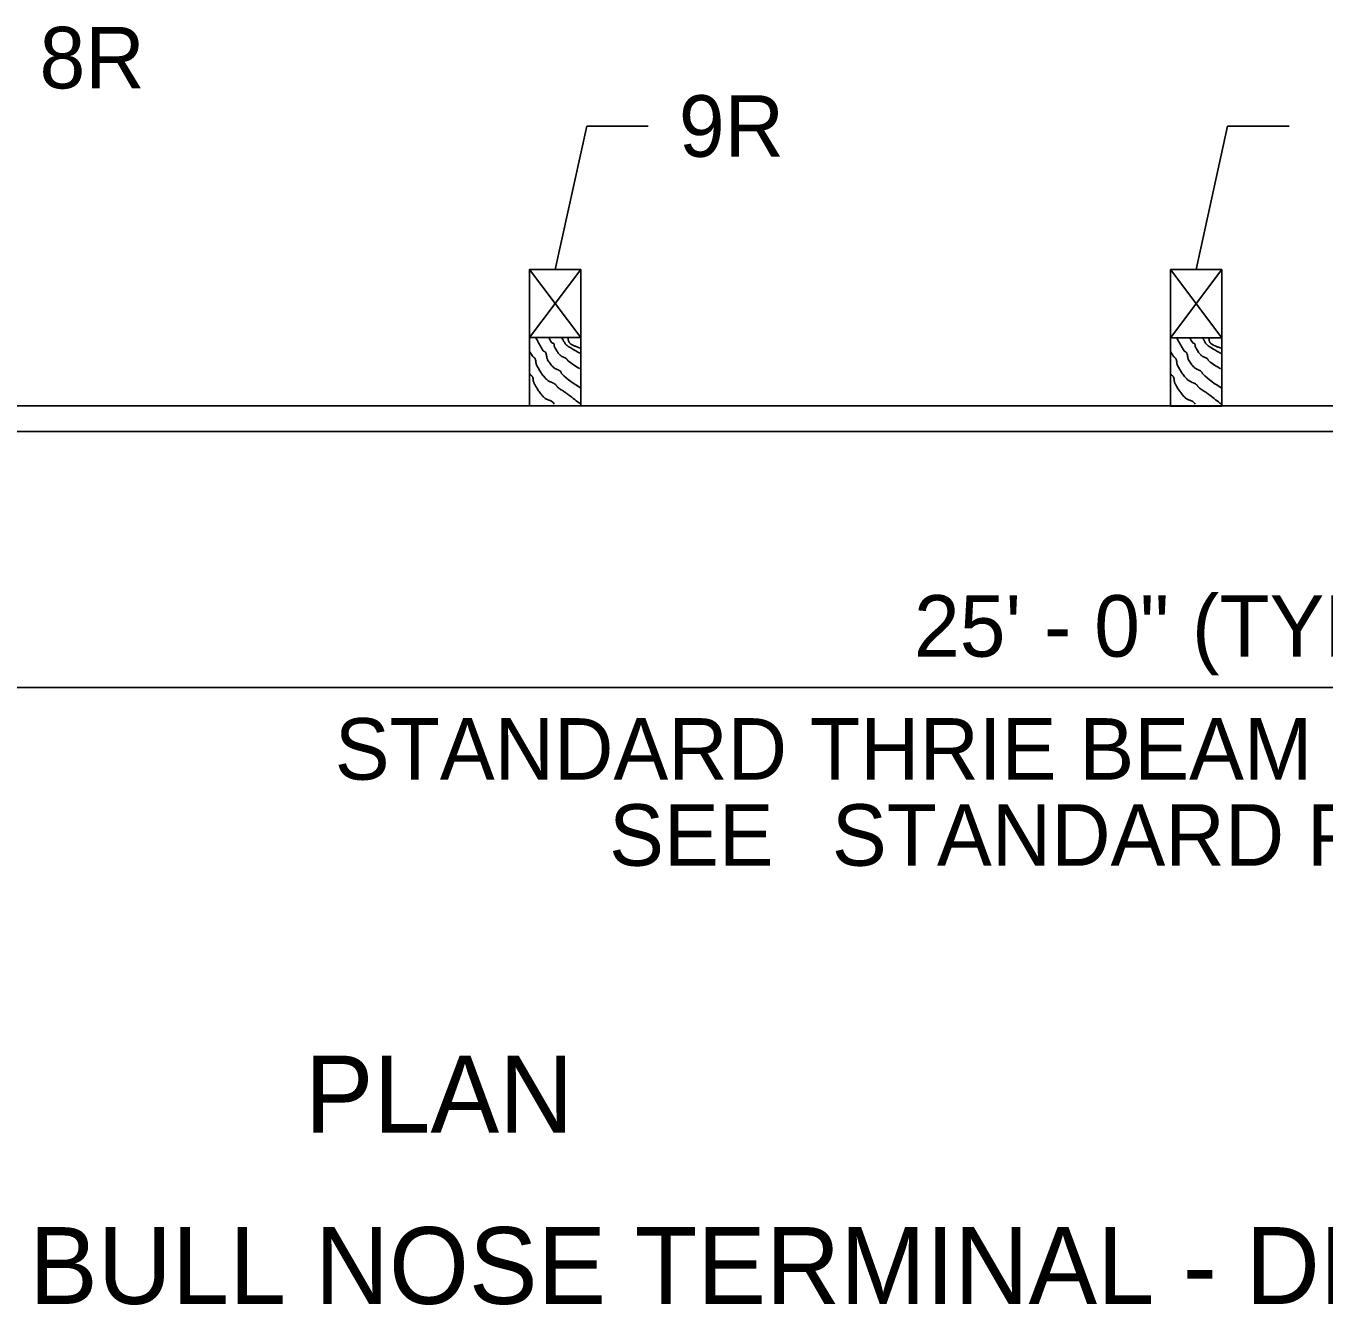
# Model space of a CAD drawing. Extents: x 1312564.2 to 1312581.5, y 1207298.4 to 1207352.6.
# Drawn here: x 1312570.058 to 1312571.742, y 1207304.86 to 1207306.519 of the extents above; entities that cross this region are included whole.
import ezdxf

# ---------------------------------------------------------------- set-up
doc = ezdxf.new("R2010")
doc.units = 0
for name, color, linetype in [('Level 13', 7, 'Continuous'), ('Level 14', 7, 'Continuous'), ('Level 15', 7, 'Continuous'), ('Level 20', 7, 'Continuous')]:
    doc.layers.add(name, color=color, linetype=linetype)

msp = doc.modelspace()

# ---------------------------------------------------------------- linework, layer by layer
at = {"layer": 'Level 13'}
for points in [[(1312570.7194039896, 1207306.1146937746), (1312570.7221586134, 1207306.1095615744), (1312570.7238268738, 1207306.106539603), (1312570.7255555, 1207306.1035501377), (1312570.727325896, 1207306.1005866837), (1312570.7291194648, 1207306.097642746), (1312570.7294023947, 1207306.0972981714), (1312570.7297603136, 1207306.0970238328), (1312570.7306033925, 1207306.096594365), (1312570.7314532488, 1207306.0961713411), (1312570.7321144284, 1207306.0955717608), (1312570.7324222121, 1207306.0950549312), (1312570.7326765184, 1207306.09451266), (1312570.7330540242, 1207306.093365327), (1312570.7334898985, 1207306.090914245), (1312570.7338912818, 1207306.0884350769), (1312570.734451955, 1207306.086687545), (1312570.7347274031, 1207306.0861443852), (1312570.7363016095, 1207306.0835514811), (1312570.738031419, 1207306.0810558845), (1312570.7399295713, 1207306.0786780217), (1312570.742008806, 1207306.076438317), (1312570.7430991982, 1207306.0755208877), (1312570.744308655, 1207306.0747590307), (1312570.746918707, 1207306.0734976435), (1312570.749506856, 1207306.0722453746), (1312570.750688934, 1207306.0714949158), (1312570.7517409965, 1207306.0705934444), (1312570.7521230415, 1207306.0699782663), (1312570.7523678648, 1207306.0692493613), (1312570.7526337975, 1207306.0685391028), (1312570.7530791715, 1207306.0679798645), (1312570.7779045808, 1207306.0494157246)], [(1312570.7362736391, 1207306.1146937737), (1312570.7401967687, 1207306.1081436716), (1312570.7404154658, 1207306.1079093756), (1312570.7407099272, 1207306.1077633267), (1312570.7414269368, 1207306.107619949), (1312570.7421493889, 1207306.1074814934), (1312570.7426788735, 1207306.1071159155), (1312570.7428199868, 1207306.1068721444), (1312570.7429332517, 1207306.106616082), (1312570.7430913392, 1207306.106073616), (1312570.7432394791, 1207306.104913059), (1312570.7433649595, 1207306.103738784), (1312570.7434947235, 1207306.1031791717), (1312570.743709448, 1207306.1026553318), (1312570.7445061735, 1207306.1011826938), (1312570.745331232, 1207306.0997201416), (1312570.7471061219, 1207306.0968591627), (1312570.7502295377, 1207306.0928550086), (1312570.7508198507, 1207306.0922347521), (1312570.7514334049, 1207306.0916307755), (1312570.7522992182, 1207306.0909426), (1312570.7532541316, 1207306.0903925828), (1312570.7553080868, 1207306.0895304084), (1312570.7573489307, 1207306.0886910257), (1312570.7587227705, 1207306.0878639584), (1312570.7589302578, 1207306.0876975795), (1312570.7591303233, 1207306.0875212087), (1312570.7596616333, 1207306.0868636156), (1312570.7601032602, 1207306.086107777), (1312570.7605681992, 1207306.0853746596), (1312570.761169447, 1207306.0847852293), (1312570.7763067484, 1207306.0745676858)], [(1312570.7531030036, 1207306.1146937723), (1312570.754498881, 1207306.1123594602), (1312570.7548076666, 1207306.1118255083), (1312570.755107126, 1207306.1112781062), (1312570.7568875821, 1207306.1079232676), (1312570.758294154, 1207306.1058972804), (1312570.7601158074, 1207306.1043224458), (1312570.7662563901, 1207306.1006090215), (1312570.776477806, 1207306.0944277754)], [(1312570.7610762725, 1207306.1146937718), (1312570.7613425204, 1207306.1129179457), (1312570.7616531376, 1207306.1111777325), (1312570.7621349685, 1207306.109574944), (1312570.7624797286, 1207306.1088569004), (1312570.7626850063, 1207306.1085242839), (1312570.7627967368, 1207306.108365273), (1312570.7628549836, 1207306.1082876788), (1312570.7628847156, 1207306.1082493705), (1312570.7628997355, 1207306.1082303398), (1312570.7629148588, 1207306.108211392), (1312570.7631970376, 1207306.107878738), (1312570.7634970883, 1207306.107560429), (1312570.76414729, 1207306.106964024), (1312570.7656234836, 1207306.1059123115), (1312570.7690821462, 1207306.1042152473), (1312570.772840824, 1207306.10275899), (1312570.774692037, 1207306.1020082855), (1312570.7764494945, 1207306.101182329)], [(1312571.5504640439, 1207306.1144906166), (1312571.5532186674, 1207306.1093584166), (1312571.5548869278, 1207306.1063364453), (1312571.5566155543, 1207306.1033469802), (1312571.55838595, 1207306.1003835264), (1312571.5601795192, 1207306.0974395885), (1312571.5604624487, 1207306.0970950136), (1312571.560820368, 1207306.096820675), (1312571.5616634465, 1207306.0963912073), (1312571.5625133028, 1207306.0959681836), (1312571.5631744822, 1207306.0953686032), (1312571.5634822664, 1207306.094851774), (1312571.5637365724, 1207306.0943095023), (1312571.5641140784, 1207306.0931621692), (1312571.5645499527, 1207306.0907110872), (1312571.5649513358, 1207306.0882319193), (1312571.565512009, 1207306.0864843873), (1312571.5657874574, 1207306.0859412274), (1312571.567361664, 1207306.0833483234), (1312571.5690914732, 1207306.0808527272), (1312571.5709896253, 1207306.0784748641), (1312571.5730688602, 1207306.0762351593), (1312571.5741592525, 1207306.07531773), (1312571.5753687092, 1207306.0745558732), (1312571.5779787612, 1207306.073294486), (1312571.5805669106, 1207306.072042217), (1312571.5817489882, 1207306.0712917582), (1312571.5828010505, 1207306.0703902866), (1312571.5831830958, 1207306.0697751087), (1312571.5834279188, 1207306.0690462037), (1312571.5836938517, 1207306.068335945), (1312571.5841392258, 1207306.0677767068), (1312571.6089646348, 1207306.0492125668)], [(1312571.5673336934, 1207306.1144906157), (1312571.571256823, 1207306.1079405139), (1312571.5714755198, 1207306.1077062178), (1312571.571769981, 1207306.1075601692), (1312571.5724869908, 1207306.1074167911), (1312571.573209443, 1207306.1072783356), (1312571.573738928, 1207306.106912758), (1312571.573880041, 1207306.1066689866), (1312571.573993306, 1207306.1064129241), (1312571.5741513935, 1207306.1058704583), (1312571.5742995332, 1207306.1047099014), (1312571.5744250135, 1207306.1035356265), (1312571.5745547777, 1207306.102976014), (1312571.5747695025, 1207306.102452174), (1312571.5755662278, 1207306.100979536), (1312571.5763912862, 1207306.0995169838), (1312571.578166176, 1207306.096656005), (1312571.581289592, 1207306.092651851), (1312571.581879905, 1207306.0920315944), (1312571.5824934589, 1207306.091427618), (1312571.5833592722, 1207306.0907394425), (1312571.584314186, 1207306.090189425), (1312571.586368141, 1207306.0893272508), (1312571.5884089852, 1207306.088487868), (1312571.5897828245, 1207306.0876608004), (1312571.589990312, 1207306.0874944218), (1312571.5901903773, 1207306.087318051), (1312571.5907216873, 1207306.086660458), (1312571.591163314, 1207306.0859046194), (1312571.5916282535, 1207306.0851715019), (1312571.5922295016, 1207306.0845820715), (1312571.6073668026, 1207306.074364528)], [(1312571.5841630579, 1207306.1144906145), (1312571.585558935, 1207306.1121563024), (1312571.5858677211, 1207306.1116223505), (1312571.5861671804, 1207306.111074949), (1312571.5879476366, 1207306.1077201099), (1312571.589354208, 1207306.1056941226), (1312571.591175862, 1207306.104119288), (1312571.5973164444, 1207306.1004058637), (1312571.60753786, 1207306.0942246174)], [(1312571.592136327, 1207306.1144906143), (1312571.5924025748, 1207306.1127147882), (1312571.5927131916, 1207306.110974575), (1312571.5931950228, 1207306.1093717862), (1312571.5935397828, 1207306.1086537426), (1312571.5937450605, 1207306.108321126), (1312571.5938567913, 1207306.1081621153), (1312571.5939150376, 1207306.108084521), (1312571.5939447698, 1207306.108046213), (1312571.5939597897, 1207306.108027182), (1312571.593974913, 1207306.1080082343), (1312571.5942570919, 1207306.1076755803), (1312571.5945571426, 1207306.1073572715), (1312571.5952073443, 1207306.1067608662), (1312571.5966835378, 1207306.105709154), (1312571.6001422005, 1207306.1040120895), (1312571.6039008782, 1207306.1025558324), (1312571.605752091, 1207306.101805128), (1312571.6075095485, 1207306.1009791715)], [(1312570.7114285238, 1207306.0971912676), (1312570.7153998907, 1207306.0904384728), (1312570.71601434, 1207306.0897307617), (1312570.7167898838, 1207306.0891536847), (1312570.7175713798, 1207306.088581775), (1312570.718203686, 1207306.0878895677), (1312570.7186999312, 1207306.0869106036), (1312570.7190302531, 1207306.0858598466), (1312570.719398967, 1207306.0836277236), (1312570.7197215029, 1207306.081362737), (1312570.7201807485, 1207306.0797444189), (1312570.7204095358, 1207306.0792344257), (1312570.7231377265, 1207306.0741542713), (1312570.7261874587, 1207306.0692772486), (1312570.729646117, 1207306.0646662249), (1312570.7315561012, 1207306.0624801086), (1312570.7325610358, 1207306.0614203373), (1312570.733601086, 1207306.060384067), (1312570.7349415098, 1207306.0592838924), (1312570.7364138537, 1207306.0583797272), (1312570.7395727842, 1207306.0569093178), (1312570.742714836, 1207306.0554726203), (1312570.7448419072, 1207306.054116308), (1312570.7454769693, 1207306.0535694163), (1312570.7461431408, 1207306.0527616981), (1312570.746709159, 1207306.0518455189), (1312570.7472963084, 1207306.0509483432), (1312570.7480258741, 1207306.0501976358), (1312570.7515893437, 1207306.0476716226), (1312570.755245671, 1207306.045261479), (1312570.7588912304, 1207306.042832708), (1312570.762422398, 1207306.040250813), (1312570.7773146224, 1207306.0285459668)], [(1312571.542488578, 1207306.0969881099), (1312571.546459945, 1207306.090235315), (1312571.5470743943, 1207306.0895276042), (1312571.547849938, 1207306.0889505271), (1312571.548631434, 1207306.0883786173), (1312571.5492637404, 1207306.0876864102), (1312571.549759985, 1207306.0867074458), (1312571.5500903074, 1207306.085656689), (1312571.5504590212, 1207306.0834245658), (1312571.5507815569, 1207306.0811595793), (1312571.5512408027, 1207306.0795412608), (1312571.5514695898, 1207306.0790312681), (1312571.5541977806, 1207306.0739511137), (1312571.557247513, 1207306.0690740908), (1312571.560706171, 1207306.0644630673), (1312571.5626161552, 1207306.062276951), (1312571.56362109, 1207306.0612171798), (1312571.5646611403, 1207306.0601809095), (1312571.5660015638, 1207306.0590807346), (1312571.5674739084, 1207306.0581765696), (1312571.5706328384, 1207306.05670616), (1312571.5737748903, 1207306.0552694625), (1312571.5759019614, 1207306.0539131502), (1312571.5765370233, 1207306.0533662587), (1312571.577203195, 1207306.0525585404), (1312571.5777692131, 1207306.051642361), (1312571.5783563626, 1207306.0507451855), (1312571.5790859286, 1207306.049994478), (1312571.582649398, 1207306.0474684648), (1312571.586305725, 1207306.0450583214), (1312571.5899512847, 1207306.04262955), (1312571.5934824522, 1207306.040047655), (1312571.608374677, 1207306.0283428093)], [(1312570.7114285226, 1207306.0681566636), (1312570.7120760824, 1207306.0670619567), (1312570.7123534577, 1207306.0666837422), (1312570.7126903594, 1207306.0663539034), (1312570.713465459, 1207306.0657766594), (1312570.714246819, 1207306.0652048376), (1312570.714591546, 1207306.064881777), (1312570.7148798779, 1207306.0645130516), (1312570.715377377, 1207306.063534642), (1312570.7157082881, 1207306.0624841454), (1312570.716076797, 1207306.060251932), (1312570.716398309, 1207306.0579864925), (1312570.7166704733, 1207306.0568944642), (1312570.7170857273, 1207306.0558579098), (1312570.7177431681, 1207306.0545727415), (1312570.7184179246, 1207306.053298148), (1312570.722889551, 1207306.0459169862), (1312570.7263514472, 1207306.041307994), (1312570.728252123, 1207306.0391160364), (1312570.7292486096, 1207306.0380509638), (1312570.7302772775, 1207306.0370075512), (1312570.7316298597, 1207306.0359255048), (1312570.7331548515, 1207306.0350798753), (1312570.7364526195, 1207306.0337565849), (1312570.7396316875, 1207306.032355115), (1312570.7410083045, 1207306.0314117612), (1312570.7421531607, 1207306.0301929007), (1312570.743244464, 1207306.0286131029)], [(1312571.5424885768, 1207306.067953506), (1312571.5431361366, 1207306.066858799), (1312571.5434135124, 1207306.0664805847), (1312571.5437504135, 1207306.0661507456), (1312571.544525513, 1207306.0655735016), (1312571.5453068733, 1207306.0650016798), (1312571.5456516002, 1207306.0646786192), (1312571.5459399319, 1207306.064309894), (1312571.5464374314, 1207306.0633314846), (1312571.5467683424, 1207306.0622809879), (1312571.5471368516, 1207306.0600487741), (1312571.547458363, 1207306.0577833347), (1312571.5477305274, 1207306.0566913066), (1312571.5481457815, 1207306.055654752), (1312571.5488032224, 1207306.0543695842), (1312571.5494779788, 1207306.0530949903), (1312571.5539496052, 1207306.0457138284), (1312571.557411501, 1207306.0411048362), (1312571.5593121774, 1207306.0389128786), (1312571.5603086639, 1207306.037847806), (1312571.561337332, 1207306.0368043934), (1312571.562689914, 1207306.035722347), (1312571.5642149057, 1207306.0348767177), (1312571.567512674, 1207306.0335534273), (1312571.5706917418, 1207306.0321519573), (1312571.5720683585, 1207306.0312086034), (1312571.573213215, 1207306.0299897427), (1312571.5743045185, 1207306.028409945)]]:
    msp.add_spline(points, degree=3, dxfattribs=at)
at = {"layer": 'Level 14'}
for p, q in [((1312570.7114285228, 1207306.1146937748), (1312570.777752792, 1207306.2031703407)), ((1312570.777752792, 1207306.114693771), (1312570.711428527, 1207306.2031703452)), ((1312571.6088128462, 1207306.1144906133), (1312571.542488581, 1207306.2029671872)), ((1312571.5424885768, 1207306.114490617), (1312571.6088128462, 1207306.202967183))]:
    msp.add_line(p, q, dxfattribs=at)
at = {"layer": 'Level 15'}
for p, q in [((1312570.7853914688, 1207306.3891097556), (1312570.7445906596, 1207306.2031703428)), ((1312570.8651201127, 1207306.3891097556), (1312570.7853914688, 1207306.3891097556)), ((1312571.616451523, 1207306.388906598), (1312571.5756507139, 1207306.2029671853)), ((1312571.6961801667, 1207306.388906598), (1312571.616451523, 1207306.388906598)), ((1312568.2576711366, 1207306.0263555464), (1312575.0870337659, 1207306.0263555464)), ((1312568.2589525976, 1207305.9928110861), (1312575.0870337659, 1207305.9928110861)), ((1312569.8758038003, 1207305.6611897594), (1312573.2317506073, 1207305.6611897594))]:
    msp.add_line(p, q, dxfattribs=at)
for points in [[(1312570.7114285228, 1207306.1146937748), (1312570.777752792, 1207306.114693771), (1312570.777752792, 1207306.2031703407), (1312570.711428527, 1207306.2031703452)], [(1312571.5424885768, 1207306.114490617), (1312571.6088128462, 1207306.1144906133), (1312571.6088128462, 1207306.202967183), (1312571.542488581, 1207306.2029671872)], [(1312570.7114285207, 1207306.0262172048), (1312570.7777527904, 1207306.0262172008), (1312570.7777527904, 1207306.114693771), (1312570.711428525, 1207306.1146937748)], [(1312571.5424885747, 1207306.026014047), (1312571.6088128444, 1207306.026014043), (1312571.6088128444, 1207306.1144906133), (1312571.5424885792, 1207306.114490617)]]:
    msp.add_lwpolyline(points, close=True, dxfattribs=at)

# ---------------------------------------------------------------- texts
at = {"layer": 'Level 20'}
for s, height, p in [('8R', 0.07972865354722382, (1312570.075931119, 1207306.437925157)), ('9R', 0.07972865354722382, (1312570.9049844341, 1207306.3492454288)), ('25\' - 0" (TYP.)', 0.07972865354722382, (1312571.2098403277, 1207305.7010540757)), ('STANDARD THRIE BEAM RAIL ELEMENTS', 0.0797286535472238, (1312570.4587734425, 1207305.541596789)), ('SEE ', 0.0797286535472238, (1312570.8144428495, 1207305.429976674)), ('STANDARD PLAN C-1a', 0.0797286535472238, (1312571.1033424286, 1207305.429976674)), ('PLAN', 0.09966079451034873, (1312570.4199589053, 1207305.084072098)), ('BEAM GUARDRAIL BULL NOSE TERMINAL - DESIGN 1', 0.0996608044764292, (1312568.8331379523, 1207304.8617824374))]:
    msp.add_text(s, height=height, dxfattribs=at).set_placement(p)

doc.saveas('drawing.dxf')
